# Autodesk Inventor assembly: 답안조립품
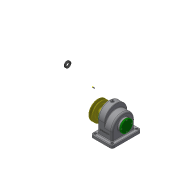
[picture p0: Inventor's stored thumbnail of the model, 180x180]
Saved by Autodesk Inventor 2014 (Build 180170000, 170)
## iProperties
Created: 2017-11
Part Number: 답안조립품
Document SubType Name: Assembly
Designer: user
Author: user
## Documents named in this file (14)
- C:\Users\user\Desktop\471108V1005\답안조립품.iam
- C:\Users\user\Desktop\471108V1005\본체.ipt
- C:\Users\user\Desktop\471108V1005\V-벨트풀리.ipt
- C:\Users\user\Desktop\471108V1005\뒤커버.ipt
- C:\Users\user\Desktop\471108V1005\멈춤나사 - M4 x 10.ipt
- 멈춤나사 - M4 x 10.ipt
- C:\Users\user\Desktop\471108V1005\베어링 6002.ipt
- C:\Users\user\Desktop\471108V1005\볼트 M3 x 8.ipt
- C:\Users\user\Desktop\471108V1005\스퍼기어.ipt
- C:\Users\user\Desktop\471108V1005\앞커버.ipt
- C:\Users\user\Desktop\471108V1005\오일 실 15 30 7.ipt
- C:\Users\user\Desktop\471108V1005\축.ipt
- C:\Users\user\Desktop\471108V1005\키 - 5 x 5 x 18.ipt
- C:\Users\user\Desktop\471108V1005\키 - 6 x 6 x 22.ipt
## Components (1 placed, 1 different names)
1. V-벨트풀리:1 — 각도:4
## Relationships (1: Angle 1)
- 각도:4 [Angle]: V-벨트풀리:1
